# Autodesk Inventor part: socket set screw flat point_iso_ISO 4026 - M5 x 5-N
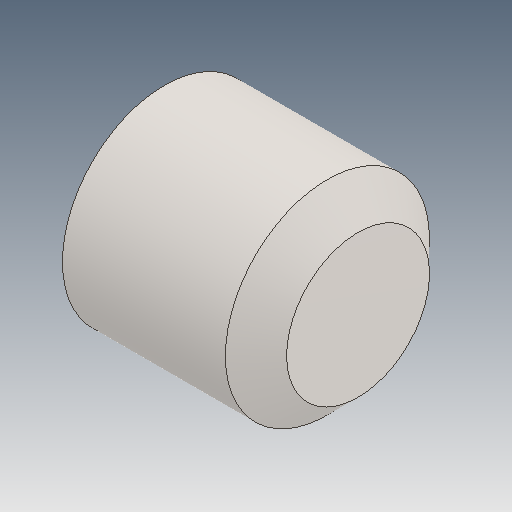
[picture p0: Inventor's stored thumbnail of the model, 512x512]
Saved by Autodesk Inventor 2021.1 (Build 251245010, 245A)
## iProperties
Created: 2021-05
Part Number: socket set screw flat point_iso_ISO 4026 - M5 x 5-N
Material: Ogólny
Document SubType Name: Modeling
Designer: user
Density: 1 g/cm^3
Appearance: Domyślna
Author: user
Revision Number: ÈÎºÎ
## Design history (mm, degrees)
feature "Hex"
node "Bryła1"
